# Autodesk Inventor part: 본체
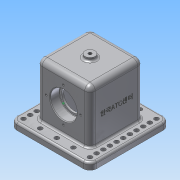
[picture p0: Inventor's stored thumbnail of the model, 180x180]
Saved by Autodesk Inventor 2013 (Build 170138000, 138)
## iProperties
Created: 2018-11
Part Number: 본체
Material: 알루미늄 6061
Document SubType Name: Modeling
Designer: Administrator
Density: 2.71 g/cm^3
Mass: 1020.76 g
Surface Area: 777.082 cm^2
Volume: 376.663 cm^3
Author: Administrator
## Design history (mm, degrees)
sketch "스케치1"
  geometry: 1 further point
sketch "스케치2"
  geometry: L1 (-40, 40)-(40, 40); L2 (40, 40)-(40, -40); L3 (40, -40)-(-40, -40); L4 (-40, -40)-(-40, 40); L5 (-40, 40)-(40, -40); L6 (40, 40)-(-40, -40); 1 further point
  constraints: 12 end point, 2 midpoint, 2 parallel, 1 horizontal, 1 perpendicular
  dimensions: "d0" = 80 distance of L1.start L1.end; "d2" = 80 distance of L1.end L2.end
extrude "돌출1" new body sketch "스케치2" distance "d3" = 80; taper "d4" = 0 deg
node "작업 평면1"
sketch "스케치3"
  geometry: L1 (-40, 80)-(40, 80) reference; C1 r 7.5 at (0, 40); 1 further point
  constraints: 1 centre point, 1 vertical alignment
  dimensions: "d6" = 15 diameter of C1; "d8" = 40 distance from line of C1.centre L1
extrude "돌출2" join sketch "스케치3" stored distance "d9" = 80; taper "d10" = 0 deg
node "작업 평면2"
sketch "스케치4"
  geometry: L1 (60, -20)-(-60, -20); L2 (-60, -20)-(-60, 100); L3 (-60, 100)-(60, 100); L4 (60, 100)-(60, -20); L5 (60, -20)-(-60, 100); L6 (-60, -20)-(60, 100); C1 r 7.5 at (0, 40) reference; 1 further point
  constraints: 12 end point, 2 midpoint, 2 parallel, 1 horizontal, 1 perpendicular
  dimensions: "d12" = 120 distance between parallel lines of L1 L3; "d14" = 120 distance between parallel lines of L4 L2
extrude "돌출3" join sketch "스케치4" distance "d15" = 10; taper "d16" = 0 deg
sketch "스케치5"
  geometry: L1 (-60, 100)-(-60, -20) reference; L2 (30, 63)-(-30, 63); L3 (-30, 63)-(-30, 17); L4 (-30, 17)-(30, 17); L5 (30, 17)-(30, 63); L6 (30, 63)-(-30, 17); L7 (-30, 63)-(30, 17); C1 r 7.5 at (0, 40) reference; 1 further point
  constraints: 12 end point, 2 midpoint, 2 parallel, 1 horizontal, 1 perpendicular
  dimensions: "d17" = 46 distance of L4.end L2.start; "d19" = 60 distance of L2.start L2.end
extrude "돌출4" cut sketch "스케치5" distance "d20" = 80; taper "d21" = 0 deg
sketch "스케치10"
  geometry: C1 r 7.5 at (0, 0) reference; 2 further points
  constraints: 1 coincident
hole "구멍1" sketch "스케치10" at (0, 0) diameter "d38" = 4.917; stored, may be unused: countersink angle "d42" = 90 deg, drill point angle "d44" = 118 deg; dims "d39" = 6, "d40" = 4, "d41" = 2, "d43" = 30
fillet "모깎기1" dims "d69" = 10
sketch "스케치13" dims "d77" = 10, "d85" = 10
  geometry: L1 (-60, 90)-(-60, -10) reference; L2 (60, -10)-(60, 90) reference; C1 r 3.3 at (-50, -10); C2 r 3.3 at (-50, 0); C3 r 3.3 at (-50, 10); C4 r 3.3 at (-50, 20); C5 r 3.3 at (-50, 30); C6 r 3.3 at (-50, 40); C7 r 3.3 at (-50, 50); C8 r 3.3 at (-50, 60); C9 r 3.3 at (-50, 70); C10 r 3.3 at (-50, 80); C11 r 3.3 at (-50, 90); C12 r 3.3 at (50, -10); C13 r 3.3 at (50, 0); C14 r 3.3 at (50, 10); C15 r 3.3 at (50, 20); C16 r 3.3 at (50, 30); C17 r 3.3 at (50, 40); C18 r 3.3 at (50, 50); C19 r 3.3 at (50, 60); C20 r 3.3 at (50, 70); C21 r 3.3 at (50, 80); C22 r 3.3 at (50, 90); C23 r 3.3 at (-25, -10); C24 r 3.3 at (0, -10); C25 r 3.3 at (25, -10); C26 r 3.3 at (-25, 90); C27 r 3.3 at (0, 90); C28 r 3.3 at (25, 90); A1 r 10 centre (-50, 90) between (-50, 100) and (-60, 90) reference; A2 r 10 centre (-50, -10) between (-60, -10) and (-50, -20) reference; A3 r 10 centre (50, -10) between (50, -20) and (60, -10) reference; 1 further point
  constraints: 28 centre point, 7 horizontal alignment, 4 equal radius, 2 coincident, 2 vertical, 40 other
  dimensions: "d70" = 6.6 diameter of C1; "d74" = 10 distance of C1.centre C2.centre; "d79" = 6.6 diameter of C12; "d82" = 10 distance of C12.centre C13.centre; "d87" = 25 distance of C23.centre A2.centre; "d89" = 25 distance of C24.centre C23.centre; "d91" = 25 distance of C26.centre A1.centre; "d93" = 25 distance of C27.centre C26.centre; "d94" = 25 distance of C28.centre C27.centre; "d95" = 25 distance of C25.centre C24.centre; "d96" = 6.6 diameter of C25; "d97" = 6.6 diameter of C27
extrude "돌출9" cut sketch "스케치13" stored distance "d98" = 3; taper "d99" = 0 deg
fillet "모깎기2" dims "d100" = 8
fillet "모깎기3" dims "d101" = 3
fillet "모깎기5" dims "d106" = 3
node "작업 평면3"
node "작업 평면4"
sketch "스케치14"
  geometry: L1 (50, -50)-(-50, -50) reference; L2 (-40, 32)-(-40, -37) reference; C1 r 20 at (0, -2); 1 further point
  constraints: 1 centre point
  dimensions: "d109" = 48 distance from line of L1 C1.centre; "d110" = 40 distance from line of L2 C1.centre; "d111" = 40 diameter of C1
extrude "돌출10" cut sketch "스케치14" distance "d112" = 14; taper "d113" = 0 deg
sketch "스케치15"
  geometry: C1 r 20 at (0, 0) reference; C2 r 16.5 at (0, 0); 1 further point
  constraints: 1 centre point, 1 coincident
  dimensions: "d114" = 33 diameter of C2
extrude "돌출11" cut sketch "스케치15" distance "d116" = 3; taper "d117" = 0 deg
sketch "스케치16"
  geometry: L1 (-50, 50)-(50, 50) reference; L2 (40, -32)-(40, 37) reference; C1 r 20 at (0, 2); 1 further point
  constraints: 1 centre point
  dimensions: "d118" = 48 distance from line of L1 C1.centre; "d119" = 40 distance from line of L2 C1.centre; "d120" = 40 diameter of C1
extrude "돌출12" cut sketch "스케치16" distance "d121" = 14; taper "d122" = 0 deg
sketch "스케치17"
  geometry: C1 r 20 at (0, 0) reference; C2 r 16.5 at (0, 0); 1 further point
  constraints: 1 centre point, 1 coincident
  dimensions: "d123" = 33 diameter of C2
extrude "돌출13" cut sketch "스케치17" distance "d125" = 3; taper "d126" = 0 deg
sketch "스케치18" dims "d127" = 52
  geometry: C1 r 20 at (0, -2) reference; 3 further points
  constraints: 2 vertical alignment, 1 coincident, 2 other
hole "구멍4" sketch "스케치18" at (0, 24) diameter "d129" = 3.242; stored, may be unused: countersink angle "d133" = 90 deg, drill point angle "d135" = 118 deg; dims "d130" = 8, "d131" = 4, "d132" = 2, "d134" = 10
sketch "스케치19" dims "d139" = 52
  geometry: C1 r 20 at (0, 2) reference; 3 further points
  constraints: 2 vertical alignment, 1 coincident, 2 other
hole "구멍5" sketch "스케치19" at (0, -24) diameter "d141" = 3.242; stored, may be unused: countersink angle "d145" = 90 deg, drill point angle "d147" = 118 deg; dims "d142" = 8, "d143" = 4, "d144" = 2, "d146" = 10
sketch "스케치20"
  geometry: L1 (82, 82)-(82, -18) reference; L2 (0, -8)-(69, -8) reference; 2 further points
  constraints: 1 other
  dimensions: "d151" = 48 distance from line of L1 point (34, 32); "d152" = 40 distance from line of L2 point (34, 32)
extrude "돌출14" join sketch "스케치20" distance "d153" = 0.5; taper "d154" = 0 deg
chamfer "모따기2" distance "d155" = 1; stored, may be unused: second distance "d156" = 2, angle "d157" = 45 deg
fillet "모깎기6" dims "d158" = 0.6
node "솔리드1"
pattern_circular "원형 패턴3" dims angle "d137" = 360 deg
pattern_circular "원형 패턴4" dims angle "d149" = 360 deg
other parameters: "d5" = 45, "d107" = -48, "d108" = -48
